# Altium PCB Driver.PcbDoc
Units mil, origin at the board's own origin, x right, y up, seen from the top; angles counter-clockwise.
Board outline 4275 x 2750 mil, 2 copper layers (Top Layer, Bottom Layer); 84 components, 44 nets, 226 pads, 191 vias.
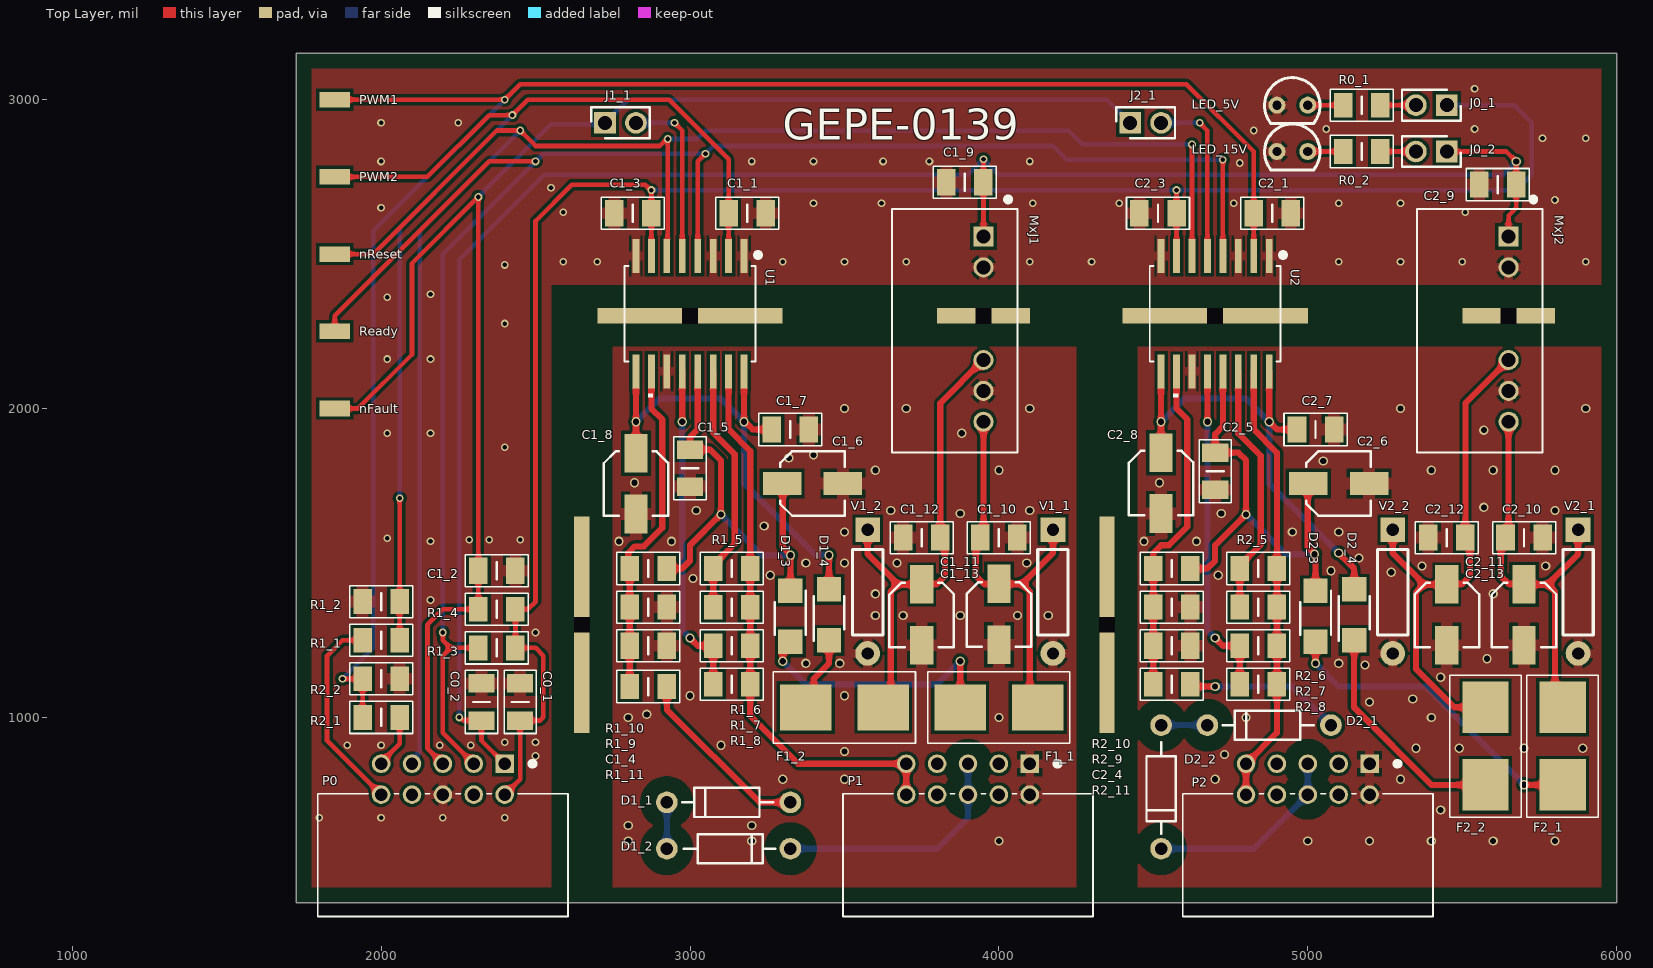
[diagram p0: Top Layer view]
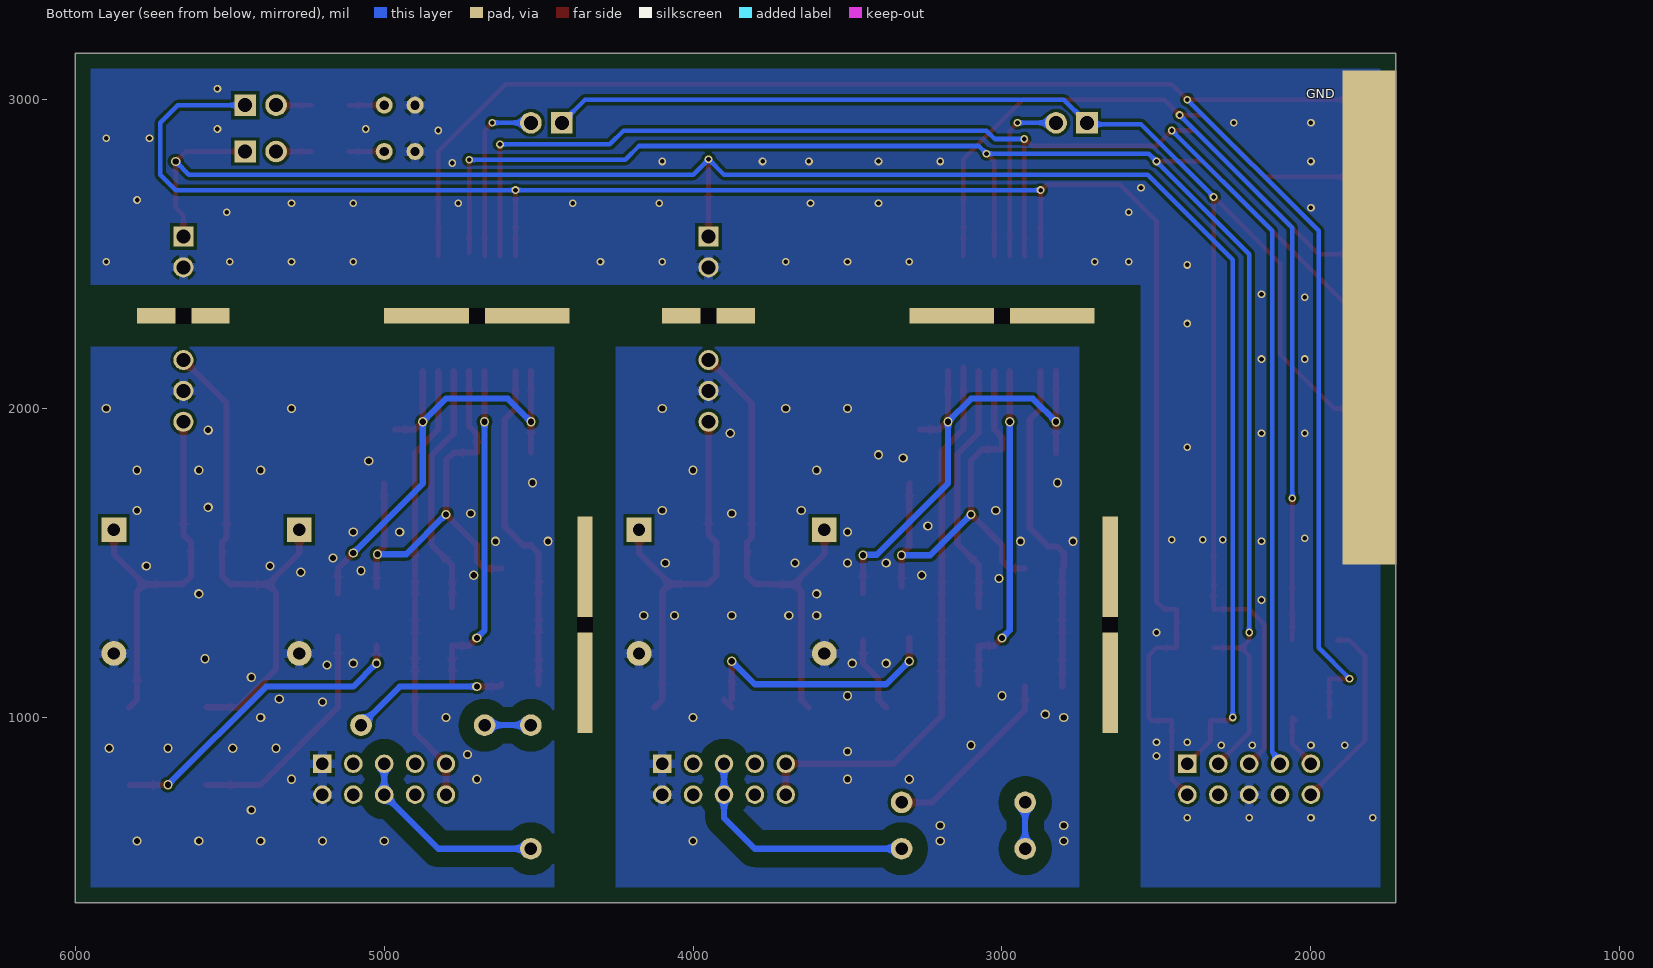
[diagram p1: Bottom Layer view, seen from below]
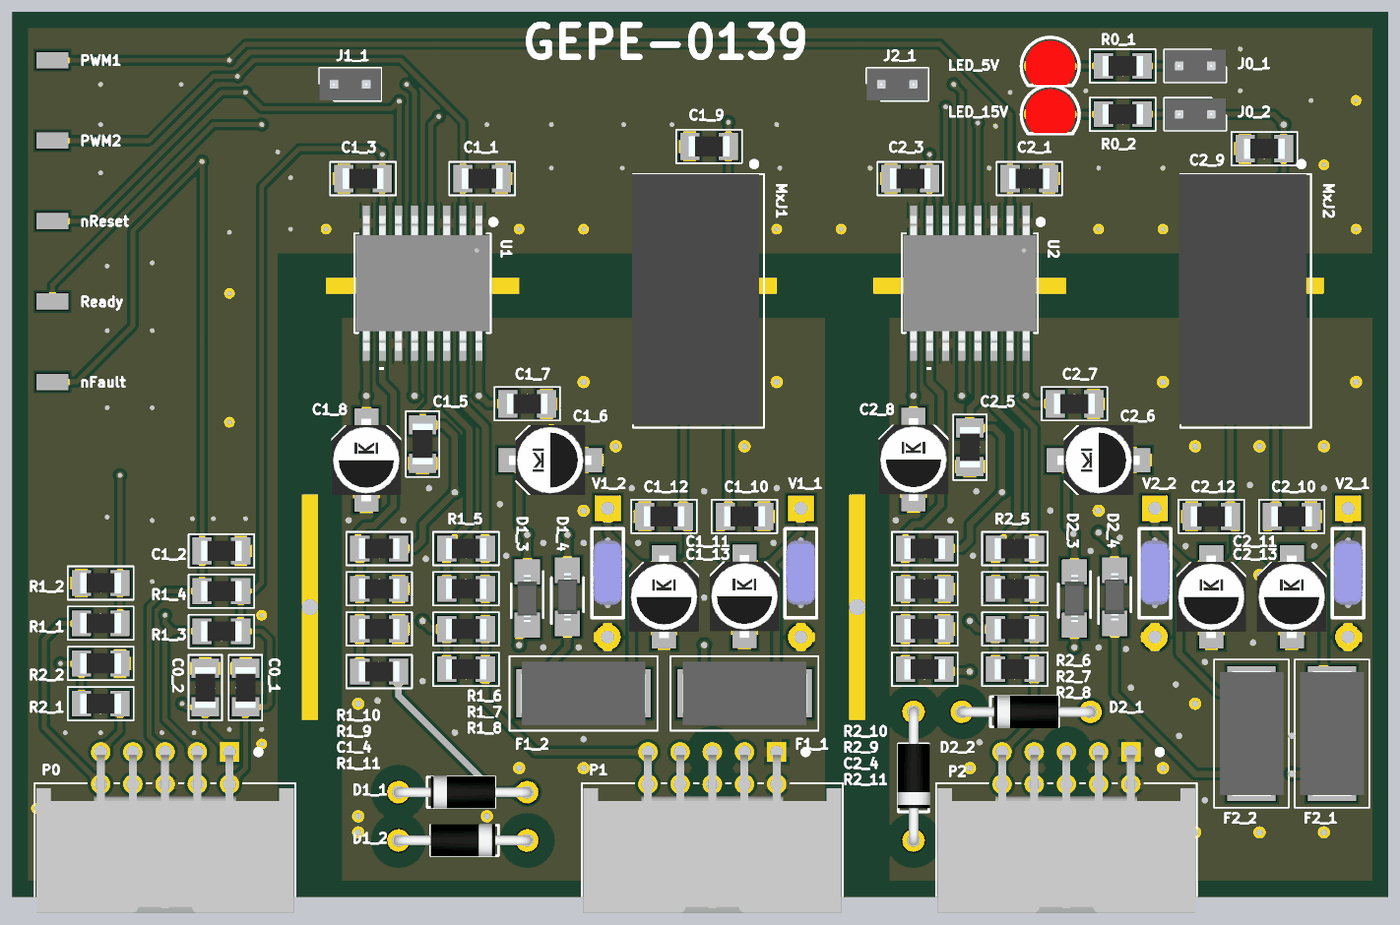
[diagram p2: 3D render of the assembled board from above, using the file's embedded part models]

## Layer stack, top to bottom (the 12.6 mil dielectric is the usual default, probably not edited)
Top Solder: solder mask 0.4, Solder Resist, Dk 3.5
Top Layer: signal copper 1.4
Dielectric 1: dielectric 12.6, FR-4, Dk 4.8
Bottom Layer: signal copper 1.4
Bottom Solder: solder mask 0.4, Solder Resist, Dk 3.5

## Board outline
1725,3150 6000,3150 6000,400 1725,400

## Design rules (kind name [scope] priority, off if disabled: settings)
Clearance Clearance_NetD1_2_1 [InNet('NetD1_2_1') vs InNet('GND_ISO1')] p1: gap=50 ignorepadtopadclearanceinfootprint=FALSE
Clearance Clearance_NetD2_1_1 [InNet('NetD2_1_1') vs InNet('GND_ISO2')] p2: gap=50 ignorepadtopadclearanceinfootprint=FALSE
Clearance Clearance_NetD2_2_1 [InNet('NetD2_2_1') vs InNet('GND_ISO2')] p3: gap=50 ignorepadtopadclearanceinfootprint=FALSE
Clearance Clearance_NetD1_1_1 [InNet('NetD1_1_1') vs InNet('GND_ISO1')] p4: gap=50 ignorepadtopadclearanceinfootprint=FALSE
Clearance "Stitching GND_ISO2" [IsStitchingVia and InNet('GND_ISO2') vs (IsVia and (Not IsStitchingVia)) Or IsPad] p5: gap=10 ignorepadtopadclearanceinfootprint=FALSE
Clearance [All] p6: gap=10 ignorepadtopadclearanceinfootprint=FALSE
ComponentClearance [All] p1: gap=-5 collisioncheckmode=3 verticalgap=10 showdistances=FALSE
DiffPairsRouting [All] p1: maxlimit=10 minlimit=10 mostfreqgap=10 substack1={C0840327-101B-4FFC-97E3-E8047B987EDC} toplayer_{c0840327-101b-4ffc-97e3-e8047b987edc}_minwidth=15 toplayer_{c0840327-101b-4ffc-97e3-e8047b987edc}_maxwidth=15 toplayer_{c0840327-101b-4ffc-97e3-e8047b987edc}_prefwidth=15 bottomlayer_{c0840327-101b-4ffc-97e3-e8047b987edc}_minwidth=15 bottomlayer_{c0840327-101b-4ffc-97e3-e8047b987edc}_maxwidth=15 bottomlayer_{c0840327-101b-4ffc-97e3-e8047b987edc}_prefwidth=15 toplayer_minwidth=15 toplayer_maxwidth=15 toplayer_prefwidth=15 bottomlayer_minwidth=15 bottomlayer_maxwidth=15 bottomlayer_prefwidth=15 substack2={2EBC8DE4-42E5-4D92-BB54-68FCB327EC1F} toplayer_{2ebc8de4-42e5-4d92-bb54-68fcb327ec1f}_minwidth=15 toplayer_{2ebc8de4-42e5-4d92-bb54-68fcb327ec1f}_maxwidth=15 toplayer_{2ebc8de4-42e5-4d92-bb54-68fcb327ec1f}_prefwidth=15 bottomlayer_{2ebc8de4-42e5-4d92-bb54-68fcb327ec1f}_minwidth=15 bottomlayer_{2ebc8de4-42e5-4d92-bb54-68fcb327ec1f}_maxwidth=15 bottomlayer_{2ebc8de4-42e5-4d92-bb54-68fcb327ec1f}_prefwidth=15 substack3={B410F142-04A1-4626-878C-5488EA430582} toplayer_{b410f142-04a1-4626-878c-5488ea430582}_minwidth=15 toplayer_{b410f142-04a1-4626-878c-5488ea430582}_maxwidth=15 toplayer_{b410f142-04a1-4626-878c-5488ea430582}_prefwidth=15 bottomlayer_{b410f142-04a1-4626-878c-5488ea430582}_minwidth=15 bottomlayer_{b410f142-04a1-4626-878c-5488ea430582}_maxwidth=15 bottomlayer_{b410f142-04a1-4626-878c-5488ea430582}_prefwidth=15 substack4={F83C5744-CF29-490E-B97B-F7943CBAD45F} toplayer_{f83c5744-cf29-490e-b97b-f7943cbad45f}_minwidth=15 toplayer_{f83c5744-cf29-490e-b97b-f7943cbad45f}_maxwidth=15 toplayer_{f83c5744-cf29-490e-b97b-f7943cbad45f}_prefwidth=15 bottomlayer_{f83c5744-cf29-490e-b97b-f7943cbad45f}_minwidth=15 bottomlayer_{f83c5744-cf29-490e-b97b-f7943cbad45f}_maxwidth=15 bottomlayer_{f83c5744-cf29-490e-b97b-f7943cbad45f}_prefwidth=15 substack5={FE27DC28-8263-47E9-9FA0-F4B9E94EB1D7} toplayer_{fe27dc28-8263-47e9-9fa0-f4b9e94eb1d7}_minwidth=15 toplayer_{fe27dc28-8263-47e9-9fa0-f4b9e94eb1d7}_maxwidth=15 toplayer_{fe27dc28-8263-47e9-9fa0-f4b9e94eb1d7}_prefwidth=15 bottomlayer_{fe27dc28-8263-47e9-9fa0-f4b9e94eb1d7}_minwidth=15 bottomlayer_{fe27dc28-8263-47e9-9fa0-f4b9e94eb1d7}_maxwidth=15 bottomlayer_{fe27dc28-8263-47e9-9fa0-f4b9e94eb1d7}_prefwidth=15 maxuncoupledlength=500
Height [All] p1: minheight=0 maxheight=10000 prefheight=500
HoleSize [All] p1: absolutevalues=TRUE maxlimit=1000 minlimit=1 maxpercent=80.000 minpercent=20.000
PolygonConnect [All] p1: connectstyle=Relief reliefconductorwidth=10 reliefentries=4 polygonreliefangle="90 Angle" airgapwidth=10
RoutingVias [All] p1: holewidth=20 width=30 viastyle="Through Hole" minholewidth=15 minwidth=25 maxholewidth=28 maxwidth=50
SilkToSilkClearance [All] p1: silktosilkclearance=0
SilkToSolderMaskClearance [IsPad] p1: minsilkscreentomaskgap=5 clearancetoexposedcopper=TRUE
SolderMaskExpansion [All] p1: expansion=4 istentingtop=FALSE
Width [All] p1: maxlimit=30 minlimit=15 preferedwidth=20 substack1={C0840327-101B-4FFC-97E3-E8047B987EDC} substack2={2EBC8DE4-42E5-4D92-BB54-68FCB327EC1F} substack3={B410F142-04A1-4626-878C-5488EA430582} substack4={F83C5744-CF29-490E-B97B-F7943CBAD45F} substack5={FE27DC28-8263-47E9-9FA0-F4B9E94EB1D7}
24 further rules are at their usual default settings.

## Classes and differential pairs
component class Driver2: ADUM2 C2_1 C2_3 C2_4 C2_5 C2_6 C2_7 C2_8 C2_9 C2_10 C2_11 C2_12 C2_13 D2_1 D2_2 D2_3 D2_4 F2_1 F2_2 MxJ2 P2 R2_1 R2_2 R2_5 R2_6 R2_7 R2_8 R2_9 R2_10 R2_11 U2 V2_1 V2_2
component class Driver: C0_1 C0_2 C1_1 C1_2 C1_3 C1_4 C1_5 C1_6 C1_7 C1_8 C1_9 C1_10 C1_11 C1_12 C1_13 D1_1 D1_2 D1_3 D1_4 F1_1 F1_2 GND J0_1 J0_2 J1_1 J2_1 LED_5V LED_15V MxJ1 nFault nReset P0 P1 PWM1 PWM2 R0_1 R0_2 R1_1 R1_2 R1_3 R1_4 R1_5 R1_6 R1_7 R1_8 R1_9 R1_10 R1_11 Ready U1 V1_1 V1_2

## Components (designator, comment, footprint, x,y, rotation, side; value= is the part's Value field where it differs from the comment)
C0_1 "CAP" CAP1206_SMD 2450,1050 r90 top
C0_2 "CAP" CAP1206_SMD 2325,1050 r90 top
C1_1 "CAP" CAP1206_SMD 3185,2632.16 r0 top
C1_2 "CAP" CAP1206_SMD 2375,1475 r0 top
C1_3 "CAP" CAP1206_SMD 2815,2632.16 r180 top
C1_4 "CAP" CAP1206_SMD 2865,1232.16 r0 top
C1_5 "CAP" CAP1206_SMD 3000,1807.16 r270 top
C1_6 "CAP" CAP_ELETRO_SMD_6.3X7.7 3396.57,1757.16 r0 top
C1_7 "CAP" CAP1206_SMD 3325,1932.16 r0 top
C1_8 "CAP" CAP_ELETRO_SMD_6.3X7.7 2825,1757.16 r270 top
C1_9 "CAP" CAP1206_SMD 3890,2732.16 r180 top
C1_10 "CAP" CAP1206_SMD 4000,1582.16 r0 top
C1_11 "CAP" CAP_ELETRO_SMD_6.3X7.7 4000,1333.73 r270 top
C1_12 "CAP" CAP1206_SMD 3750,1582.16 r180 top
C1_13 "CAP" CAP_ELETRO_SMD_6.3X7.7 3750,1332.16 r270 top
C2_1 "CAP" CAP1206_SMD 4885,2632.16 r0 top
C2_3 "CAP" CAP1206_SMD 4515,2632.16 r180 top
C2_4 "CAP" CAP1206_SMD 4560,1232.16 r0 top
C2_5 "CAP" CAP1206_SMD 4700,1797.16 r270 top
C2_6 "CAP" CAP_ELETRO_SMD_6.3X7.7 5100,1757.16 r0 top
C2_7 "CAP" CAP1206_SMD 5025,1932.16 r0 top
C2_8 "CAP" CAP_ELETRO_SMD_6.3X7.7 4525,1758.73 r270 top
C2_9 "CAP" CAP1206_SMD 5615,2725 r180 top
C2_10 "CAP" CAP1206_SMD 5700,1582.16 r0 top
C2_11 "CAP" CAP_ELETRO_SMD_6.3X7.7 5700,1332.16 r270 top
C2_12 "CAP" CAP1206_SMD 5450,1582.16 r180 top
C2_13 "CAP" CAP_ELETRO_SMD_6.3X7.7 5450,1332.16 r270 top
D1_1 "TLHR5400-AS12Z" DIODE_TH_10.1 2925,725 r0 top
D1_2 "TLHR5400-AS12Z" DIODE_TH_10.1 3325,575 r180 top
D1_3 "TLHR5400-AS12Z" DIODE_SMD_SOD123 3325,1327.16 r270 top
D1_4 "TLHR5400-AS12Z" DIODE_SMD_SOD123 3450,1332.16 r90 top
D2_1 "TLHR5400-AS12Z" DIODE_TH_10.1 4675,975 r0 top
D2_2 "TLHR5400-AS12Z" DIODE_TH_10.1 4525,575 r90 top
D2_3 "TLHR5400-AS12Z" DIODE_SMD_SOD123 5025,1327.16 r270 top
D2_4 "TLHR5400-AS12Z" DIODE_SMD_SOD123 5150,1332.16 r90 top
F1_1 "Fuse_0154" FUSE_0154 4000,1032.16 r180 top
F1_2 "Fuse_0154" FUSE_0154 3500,1032.16 r180 top
F2_1 "Fuse_0154" FUSE_0154 5825,907.16 r270 top
F2_2 "Fuse_0154" FUSE_0154 5575,907.16 r270 top
GND "TB004-508-02BE" TestPoint 1810,2295 r0 top
J0_1 "TB004-508-02BE" HEADER_MALE_TH_2P_2.54 5450,2982.16 r90 top
J0_2 "TB004-508-02BE" HEADER_MALE_TH_2P_2.54 5450,2832.16 r90 top
J1_1 "TB004-508-02BE" HEADER_MALE_TH_2P_2.54 2725,2925 r270 top
J2_1 "TB004-508-02BE" HEADER_MALE_TH_2P_2.54 4425,2925 r270 top
LED_5V "TLHR5400-AS12Z" "LED_TH_2.54 (SMALL)" 4900,2982.16 r0 top
LED_15V "TLHR5400-AS12Z" "LED_TH_2.54 (SMALL)" 4900,2832.16 r0 top
MxJ1 "MGJ2D152005SC" MGJ2_MUR 3950,2557.16 r270 top
MxJ2 "MGJ2D152005SC" MGJ2_MUR 5650,2557.16 r270 top
nFault "TB004-508-02BE" TESTPOINT 1850,2000 r270 top
nReset "TB004-508-02BE" TESTPOINT 1850,2500 r270 top
P0 "5103311-1" CONN_5103311-1_TYC 2400,750 r180 top
P1 "5103311-1" CONN_5103311-1_TYC 4100,750 r180 top
P2 "5103311-1" CONN_5103311-1_TYC 5200,750 r180 top
PWM1 "TB004-508-02BE" TESTPOINT 1850,3000 r270 top
PWM2 "TB004-508-02BE" TESTPOINT 1850,2750 r270 top
R0_1 "" RESIS_SMD_1206 5175,2982.16 r0 top
R0_2 "" RESIS_SMD_1206 5175,2832.16 r0 top
R1_1 "" RESIS_SMD_1206 2000,1250 r0 top
R1_2 "" RESIS_SMD_1206 2000,1375 r0 top
R1_3 "" RESIS_SMD_1206 2375,1225 r0 top
R1_4 "" RESIS_SMD_1206 2375,1350 r0 top
R1_5 "Res1" RESIS_SMD_1206 3135,1482.14 r0 top
R1_6 "Res1" RESIS_SMD_1206 3135,1357.14 r0 top
R1_7 "Res1" RESIS_SMD_1206 3135,1232.14 r0 top
R1_8 "Res1" RESIS_SMD_1206 3135,1107.14 r0 top
R1_9 "" RESIS_SMD_1206 2865,1357.16 r180 top
R1_10 "" RESIS_SMD_1206 2865,1482.16 r0 top
R1_11 "" RESIS_SMD_1206 2865,1100 r0 top
R2_1 "" RESIS_SMD_1206 2000,1000 r180 top
R2_2 "" RESIS_SMD_1206 2000,1125 r180 top
R2_5 "Res1" RESIS_SMD_1206 4840,1482.16 r0 top
R2_6 "Res1" RESIS_SMD_1206 4840,1357.16 r0 top
R2_7 "Res1" RESIS_SMD_1206 4840,1232.16 r0 top
R2_8 "Res1" RESIS_SMD_1206 4840,1107.16 r0 top
R2_9 "" RESIS_SMD_1206 4560,1357.16 r180 top
R2_10 "" RESIS_SMD_1206 4560,1482.16 r0 top
R2_11 "" RESIS_SMD_1206 4560,1107.16 r0 top
Ready "TB004-508-02BE" TESTPOINT 1850,2250 r90 top
U1 "ADUM4135BRWZ" RW_16_ADI-M 3000,2307.16 r270 top
U2 "ADUM4135BRWZ" RW_16_ADI-M 4700,2307.16 r270 top
V1_1 "B72220S131K101" VARIST 4175,1407.16 r270 top
V1_2 "B72220S131K101" VARIST 3575,1407.16 r270 top
V2_1 "B72220S131K101" VARIST 5875,1407.16 r270 top
V2_2 "B72220S131K101" VARIST 5275,1407.16 r270 top

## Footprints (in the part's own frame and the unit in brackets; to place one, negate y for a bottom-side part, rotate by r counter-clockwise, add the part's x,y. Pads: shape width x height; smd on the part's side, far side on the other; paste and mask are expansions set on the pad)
CAP1206_SMD [mil]
  rect 60x85 smd: 1(-60,0) 2(60,0)
  silkscreen extent -102,-52 102,52, body extent -63,-31 63,31, height 26
CAP_ELETRO_SMD_6.3X7.7 [mm]
  rect 3.175x1.905 smd: 1(-2.5,0) 2(2.5,0)
  silkscreen extent -2.65,-2.65 2.65,2.65, body extent -3.25,-2.75 3.25,2.75, height 5.74
CONN_5103311-1_TYC [mil]
  rect 60x60 hole 40 mask+0: 1(0,-100)
  round 60 hole 40 mask+0: 2(0,0) 3(100,-100) 4(100,0) 5(200,-100) 6(200,0) 7(300,-100) 8(300,0) 9(400,-100) 10(400,0)
  silkscreen extent -205,-101 605,395, body extent -200,-90 600,400, height 370
DIODE_SMD_SOD123 [mm]
  rect 2x2 smd: 1(-2.1,0) 2(2.1,0)
  silkscreen extent -2.13,-1.27 1.52,1.27, body extent -1.85,-0.77 1.85,0.78, height 1.45
DIODE_TH_10.1 [mil]
  round 70 hole 40: 1(0,0) 2(400,0)
  silkscreen extent 49,-47 345,47, body extent -15,-51 415,50, height 100
FUSE_0154 [mil]
  rect 167x150 smd: 1(-125.59,0) 2(125.59,0)
  silkscreen extent -230,-116 230,116, body extent -194,-99 194,99, height 154
HEADER_MALE_TH_2P_2.54 [mil]
  rect 70x70 hole 45: 1(0,0)
  round 70 hole 45: 2(0,100)
  silkscreen extent -50,-45 50,145, body extent -50,-45 50,145, height 338
"LED_TH_2.54 (SMALL)" [mil]
  round 55 hole 30: 1(0,0) 2(100,0)
  silkscreen extent -40,-60 140,89, body extent -28,-59 129,79, height 212
MGJ2_MUR [mil]
  rect 65x65 hole 45 mask+0: 1(0,0)
  round 65 hole 45 mask+0: 2(100,0) 5(400,0) 6(500,0) 7(600,0)
  silkscreen extent -121,-296 699,110, body extent -89,-300 689,96, height 502
RESIS_SMD_1206 [mil]
  rect 60x80 smd: 1(-60,0) 2(60,0)
  silkscreen extent -102,-52 102,52, body extent -63,-31 63,31, height 30
RW_16_ADI-M [mil]
  rect 110x22 smd paste+0 mask+0: 1(-186.5,175) 2(-186.5,125) 3(-186.5,75) 4(-186.5,25) 5(-186.5,-25) 6(-186.5,-75) 7(-186.5,-125) 8(-186.5,-175) 9(186.5,-175) 10(186.5,-125) 11(186.5,-75) 12(186.5,-25) 13(186.5,25) 14(186.5,75) 15(186.5,125) 16(186.5,175)
  silkscreen extent -191,-212 270,221, body extent -209,-206 209,206, height 104
TestPoint [mil]
  rect 175x1600 smd far side: 1(0,0)
TESTPOINT [mm]
  rect 1.28x2.5 smd: 1(0,0)
VARIST [mil]
  rect 80x80 hole 40: 1(-200,0)
  round 80 hole 40: 2(200,0)
  silkscreen extent -137,-49 140,49, body extent -110,-45 110,45, height 250

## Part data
C0_1 C0_2 C1_1 C1_2 C1_3 C1_4 C1_5 C1_6 C1_7 C1_8 C1_9 C1_10 C1_11 C1_12 C1_13 C2_1 C2_3 C2_4 C2_5 C2_6 C2_7 C2_8 C2_9 C2_10 C2_11 C2_12 C2_13: "Capacitor", Manufacturer_Name=Kemet, Manufacturer_Part_Number=C1206X475K3RACAUTO7210, Mouser Part Number=80-C1206X475K3RAUTLR
D1_1 D1_2 D1_3 D1_4 D2_1 D2_2 D2_3 D2_4: library part Diode, "Diode", Manufacturer_Name=Vishay
F1_1 F1_2 F2_1 F2_2: "Fuse", Manufacturer_Name=LITTELFUSE, Manufacturer_Part_Number=0154002.DRL, Mouser2 Part Number=576-0154002.DRL
GND nFault nReset PWM1 PWM2 Ready: library part TestPoint, "Connector", Manufacturer_Name="CUI Devices", Mouser Part Number=490-TB004-508-02BE
J0_1 J0_2 J1_1 J2_1: library part Con_Header_2P, "Connector", Manufacturer_Name="CUI Devices", Mouser Part Number=490-TB004-508-02BE
LED_5V LED_15V: library part LED, "LED", Manufacturer_Name=Vishay
MxJ1 MxJ2: "No Description Available", Mfr_Name=Murata
P0 P1 P2: library part Con_Header_5103311-1, "No Description Available", Mfr_Name="TE Connectivity"
R0_1 R0_2 R1_1 R1_2 R1_3 R1_4 R1_5 R1_6 R1_7 R1_8 R1_9 R1_10 R1_11 R2_1 R2_2 R2_5 R2_6 R2_7 R2_8 R2_9 R2_10 R2_11: library part Resistor, "Resistor"
U1 U2: "No Description Available", Mfr_Name="Analog Devices Inc"
V1_1 V1_2 V2_1 V2_2: library part Varistor, "No Description Available", Mfr_Name=TDK

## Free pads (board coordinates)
  rect 50x700 hole 50 square mask+0: 1(2650,1300) 1(4350,1300)
  rect 600x50 hole 50 square mask+0: 1(3000,2300) 1(4700,2300)
  rect 300x50 hole 50 square mask+0: 1(3950,2300) 1(5650,2300)

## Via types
v1: diameter 30, hole 20, Top Layer to Bottom Layer, tented top, 75 vias
v2: diameter 25, hole 15, Top Layer to Bottom Layer, tented top, 63 vias
v3: diameter 30, hole 20, Top Layer to Bottom Layer, 33 vias
v4: diameter 25, hole 15, Top Layer to Bottom Layer, 20 vias

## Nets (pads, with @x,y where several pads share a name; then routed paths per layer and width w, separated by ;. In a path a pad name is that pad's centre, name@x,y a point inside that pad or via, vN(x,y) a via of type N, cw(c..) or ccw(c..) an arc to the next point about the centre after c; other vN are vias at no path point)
GND: C0_1.2 C0_2.2 C1_1.2 C1_2.2 C1_3.2 C1_9.2 C2_1.2 C2_3.2 C2_9.2 GND.1 LED_5V.1 LED_15V.1 MxJ1.2 MxJ2.2 P0.6 R1_2.1 R2_2.1 U1.1 U1.3 U1.8 U2.1 U2.3 U2.8
  other v2: 1890,910 2000,910 2190,910 2290,910 2400,920 2500,920 2160,1380 2160,1570 2285,1575 2350,1575 2450,1575 2020,1580 2020,1920 2160,1920 2020,2160 2160,2160 2020,2360 2160,2370 2400,2465 2590,2475 2590,2635 5510,2635 2000,2650 3400,2665 3620,2665 4110,2665 4390,2665 4760,2665 5100,2665 5300,2665 2550,2715 4780,2795 2000,2800 3200,2800 3400,2800 3625,2800 3775,2800 4100,2800 5760,2875 4825,2900 5060,2905 5540,2905 2000,2925 2250,2925 5540,3035
  other v4: 1800,675 2000,675 2200,675 2400,675 2500,875 2500,1275 2400,1875 2400,2275 2700,2475 3300,2475 3500,2475 3700,2475 4100,2475 4300,2475 5100,2475 5300,2475 5500,2475 5900,2475 5800,2675 5900,2875
GND_ISO1: C1_4.2 C1_5.2 C1_6.2 C1_7.2 C1_8.2 C1_10.2 C1_11.2 C1_12.2 C1_13.2 MxJ1.6 P1.1 P1.2 R1_9.1 U1.11 V1_1.2 V1_2.2
  other v1: 3500,890 3100,910 2860,1010 3000,1070 3500,1070 3375,1175 3485,1175 3600,1330 3690,1330 3875,1330 4060,1330 4160,1330 3010,1450 3260,1460 3375,1500 3500,1500 3670,1500 4090,1500 2770,1570 2940,1570 3240,1620 3875,1660 3020,1670 3650,1670 4100,1670 2820,1760 3320,1840 3880,1920
  other v3: 2800,600 3200,600 4000,600 2800,650 3200,650 3300,800 3500,800 2800,1000 4000,1000 3600,1400 3500,1600 3600,1800 4000,1800 3400,1850 3500,2000 3700,2000 4100,2000
GND_ISO2: C2_4.2 C2_5.2 C2_6.2 C2_7.2 C2_8.2 C2_10.2 C2_11.2 C2_12.2 C2_13.2 MxJ2.6 P2.1 P2.2 R2_9.1 U2.11 V2_1.2 V2_2.2
  other v1: 5430,700 4730,880 5350,900 5490,900 5700,900 5890,900 5200,1050 5340,1060 5430,1130 5185,1170 5100,1175 5580,1190 4710,1460 5270,1470 5075,1475 5370,1490 5770,1490 5165.83,1515.83 4470,1570 4640,1570 4950,1600 4720,1660 5800,1670 5570,1680 4520,1760 5050,1830 5570,1930
  other v3: 5000,600 5200,600 5400,600 5600,600 5800,600 4700,800 5300,800 4800,1000 5400,1000 5600,1400 5100,1600 5400,1800 5600,1800 5800,1800 5300,2000 5900,2000
NetC0_1_1: C0_1.1 C1_3.1 C2_3.1 J0_1.1 P0.2 R1_3.2 R1_4.2 U1.7 U2.7 | length 6268.2
  Top Layer w15: P0.2 2450,800 C0_1.1 2515,990 2525,1000 2525,1200 2500,1225 R1_3.2 R1_4.2 2475,1350 2500,1375 2500,2607.16 2617.84,2725 2854.45,2725 2872.29,2707.16 v2(2875,2707.16) C1_3.1 U1.7 ; U2.7 C2_3.1 v2(4575,2707.16)
  Bottom Layer w15: v2(2875,2707.16) v2(4575,2707.16) 5675,2707.16 5725,2757.16 5725,2925 5667.84,2982.16 J0_1.1
NetC0_2_1: C0_2.1 C1_9.1 C2_9.1 J0_2.1 MxJ1.1 MxJ2.1 P0.1 | length 6065.7
  Top Layer w15: v2(2253.12,1000) 2255.83,1000 2265.83,990 C0_2.1 2325,925 P0.1 ; MxJ1.1 C1_9.1 v2(3950,2807.16) ; J0_2.1 5642.84,2832.16 v1(5675,2800) C2_9.1 5675,2650 5650,2625 MxJ2.1
  Bottom Layer w15: v2(2253.12,1000) 2253.12,2482.16 2528.12,2757.16 3900,2757.16 v2(3950,2807.16) 4000,2757.16 5632.16,2757.16 v1(5675,2800)
NetC1_1_1: C1_1.1 PWM2.1 R1_1.2 R1_2.2 U1.2 | length 3623.1
  Top Layer w15: PWM2.1 2150,2750 2350,2950 v2(2425,2950) 2475,3000 2932.16,3000 3125,2807.16 C1_1.1 U1.2 ; R1_1.2 R1_2.2 v2(2060,1710)
  Bottom Layer w15: v2(2060,1710) 2060,2585 v2(2425,2950)
NetC1_2_1: C1_2.1 J1_1.1 J2_1.1 nFault.1 P0.5 R1_4.1 | length 5184.5
  Top Layer w15: nFault.1 1925,2000 2100,2175 2100,2470 v2(2315,2685) C1_2.1 R1_4.1 2200,1350 2150,1300 2150,900 P0.5
  Bottom Layer w15: v2(2315,2685) 2550,2920 2720,2920 J1_1.1 2800,3000 4350,3000 J2_1.1
NetC1_4_1: C1_4.1 R1_9.2 R1_10.1 R1_11.1 U1.10 | length 1099.5
  Top Layer w20: R1_11.1 C1_4.1 R1_9.2 R1_10.1 2800,1487.16 2800,1532.16 2821.42,1553.58 2850,1553.58 2910,1613.58 2910,1965 2875,2000 U1.10
NetC1_5_1: C1_5.1 C1_6.1 D1_3.1 R1_10.2 U1.13 | length 1456
  Top Layer w20: R1_10.2 2975,1482.16 3000,1507.16 3000,1557.16 v1(3100,1657.16) 3100,1832.16 3065,1867.16 C1_5.1 3000,1907.16 3025,1932.16 U1.13 ; C1_6.1 3300,1755.31 3300,1552.71 3325,1527.71 D1_3.1@3325,1422.16
  Bottom Layer w20: v1(3100,1657.16) 3232.16,1525 v1(3325,1525)
NetC1_7_1: C1_7.1 C1_8.1 D1_4.2 U1.9 U1.16 | length 1634.9
  Top Layer w20: C1_8.1 v1(2825,1957.16) U1.9 ; U1.16 v1(3175,1957.16) 3177.71,1957.16 3202.71,1932.16 C1_7.1 ; D1_4.2@3450,1402.33 v1(3450,1525)
  Bottom Layer w20: v1(2825,1957.16) 2900,2032.16 3100,2032.16 v1(3175,1957.16) 3175,1757.16 3405.24,1526.91 3448.09,1526.91 v1(3450,1525)
NetC1_10_1: C1_10.1 C1_11.1 F1_1.1 MxJ1.7 V1_1.1 | length 1307.1
  Top Layer w20: MxJ1.7 3950,1592.16 C1_10.1 3925,1567.16 3925,1458.87 3951.72,1432.16 C1_11.1 4075,1432.16 ; F1_1.1 4100,1057.75 4100,1407.16 4075,1432.16 ; V1_1.1 4175,1532.16 4075,1432.16
NetC1_12_1: C1_12.1 C1_13.1 F1_2.1 MxJ1.5 V1_2.1 | length 1562.4
  Top Layer w20: V1_2.1 3575,1529.01 3673.43,1430.58 ; F1_2.1 3650,1056.57 3650,1407.16 3673.43,1430.58 ; MxJ1.5 3810,2017.16 C1_12.1 3825,1567.16 3825,1457.16 3800,1432.16 3751.57,1432.16 C1_13.1 3673.43,1430.58
NetC2_1_1: C2_1.1 PWM1.1 R2_1.2 R2_2.2 U2.2 | length 5706.9
  Top Layer w15: PWM1.1 v2(2400,3000) 2450,3050 4607.16,3050 4825,2832.16 C2_1.1 U2.2 ; v2(1875,1125) R2_2.2 R2_1.2
  Bottom Layer w15: v2(1875,1125) 1975,1225 1975,2575 v2(2400,3000)
NetC2_4_1: C2_4.1 R2_9.2 R2_10.1 R2_11.1 U2.10 | length 1088.3
  Top Layer w20: R2_11.1 C2_4.1 R2_9.2 R2_10.1 4500,1532.16 4525,1557.16 4550.13,1557.16 4610,1617.02 4610,1965 4575,2000 U2.10
NetC2_5_1: C2_5.1 C2_6.1 D2_3.1 R2_10.2 U2.13 | length 1463.2
  Top Layer w20: R2_10.2 4675,1482.16 4700,1507.16 4700,1557.16 v1(4800,1657.16) 4800,1832.16 4775,1857.16 C2_5.1 4700,1917.16 4725,1942.16 U2.13 ; C2_6.1 5000,1755.58 5000,1552.71 5024.98,1527.72 5024.98,1525.02 5023.63,1523.66 5025,1522.29 D2_3.1@5025,1422.16
  Bottom Layer w20: v1(4800,1657.16) 4928.87,1528.28 v1(5021.72,1528.28)
NetC2_7_1: C2_7.1 C2_8.1 D2_4.2 U2.9 U2.16 | length 1608.4
  Top Layer w20: C2_8.1 v1(4525,1957.16) U2.9 ; U2.16 v1(4875,1957.16) 4900,1932.16 C2_7.1 ; v1(5100,1532.16) 5150,1482.16 D2_4.2@5150,1402.15
  Bottom Layer w20: v1(4525,1957.16) 4600,2032.16 4800,2032.16 v1(4875,1957.16) 4875,1757.16 v1(5100,1532.16)
NetC2_10_1: C2_10.1 C2_11.1 F2_1.1 MxJ2.7 V2_1.1 | length 1309
  Top Layer w20: MxJ2.7 5650,1592.16 C2_10.1 5625,1567.16 5625,1457.16 5650,1432.16 5698.43,1432.16 C2_11.1 5776.57,1430.58 ; F2_1.1@5825.59,1032.16 5800,1057.75 5800,1407.16 5776.57,1430.58 ; V2_1.1 5875,1529.01 5776.57,1430.58
NetC2_12_1: C2_12.1 C2_13.1 F2_2.1 MxJ2.5 V2_2.1 | length 1703.2
  Top Layer w20: V2_2.1 5275,1532.16 5376.57,1430.58 ; F2_2.1 5474.41,1032.75 5350,1157.16 5350,1404.01 5376.57,1430.58 ; MxJ2.5 5510,2017.16 C2_12.1 5525,1567.16 5525,1457.16 5500,1432.16 5451.57,1432.16 C2_13.1 5376.57,1430.58
NetD1_1_1: D1_1.1 D1_2.2 | length 150
  Bottom Layer w20: D1_2.2 D1_1.1
NetD1_1_2: D1_1.2 R1_11.2 | length 599.3
  Top Layer w20: R1_11.2 2925,1025 3225,725 D1_1.2
NetD1_2_1: D1_2.1 P1.5 P1.6 | length 791.4
  Bottom Layer w20: D1_2.1 3800,575 3900,675 P1.6 P1.5
NetD1_3_2: D1_3.2 F1_1.2 | length 872.7
  Top Layer w20: v1(3300,1182.16) D1_3.2@3300,1257.16 ; F1_1.2 F1_1.2@3900,1057.75 ; F1_1.2@3875,1057.75 v1(3875,1182.16)
  Bottom Layer w20: v1(3300,1182.16) 3375,1107.16 3800,1107.16 v1(3875,1182.16)
NetD1_4_1: D1_4.1 F1_2.2 | length 248.6
  Top Layer w20: F1_2.2 3400.44,1058.19 3400.44,1125.44 3450,1175 D1_4.1
NetD2_1_1: D2_1.1 D2_2.2 | length 174.5
  Top Layer w20: D2_2.2 D2_2.2@4549.47,975
  Bottom Layer w20: D2_2.2 D2_1.1
NetD2_1_2: D2_1.2 R2_11.2 | length 509.7
  Top Layer w20: R2_11.2 4627.16,1100 v1(4700,1100)
  Bottom Layer w20: v1(4700,1100) 4950,1100 D2_1.2
NetD2_2_1: D2_2.1 P2.5 P2.6 | length 647.5
  Bottom Layer w20: D2_2.1 4825,575 P2.6 P2.5
NetD2_3_2: D2_3.2 F2_1.2 | length 1020.1
  Top Layer w20: v1(5025,1175) D2_3.2@5025,1232.16 ; v1(5700,782.16) 5700.59,781.57 F2_1.2
  Bottom Layer w20: v1(5025,1175) 5100,1100 5382.16,1100 v1(5700,782.16)
NetD2_4_1: D2_4.1 F2_2.2 | length 758.2
  Top Layer w20: D2_4.1@5150,1261.6 5150,1032.16 5400,782.16 5400.59,781.57 F2_2.2
NetJ0_1_2: J0_1.2 R0_1.2 | length 115
  Top Layer w15: R0_1.2 J0_1.2
NetJ0_2_2: J0_2.2 R0_2.2 | length 115
  Top Layer w15: R0_2.2 J0_2.2
NetJ1_1_2: J1_1.2 U1.5 | length 576.5
  Top Layer w15: v2(2950,2925) 2975,2900 U1.5
  Bottom Layer w15: J1_1.2@2825,2900 J1_1.2@2830,2905 ; J1_1.2 v2(2950,2925) v2@2950,2922.29
NetJ2_1_2: J2_1.2 U2.5 | length 577.1
  Top Layer w15: v2(4650,2925) 4675,2900 U2.5
  Bottom Layer w15: J2_1.2@4525,2900 4550,2925 v2(4650,2925)
NetLED_5V_2: LED_5V.2 R0_1.1 | length 115
  Top Layer w15: LED_5V.2 R0_1.1
NetLED_15V_2: LED_15V.2 R0_2.1 | length 115
  Top Layer w15: LED_15V.2 R0_2.1
NetnReset_1: nReset.1 P0.7 U1.6 U2.6 | length 5937.7
  Top Layer w15: nReset.1 1975,2500 2375,2900 v2(2450,2900) 2500,2850 2902.29,2850 2924.79,2872.5 v2(2927.5,2872.5) 2927.5,2496.16 U1.6 ; U2.6 4623.75,2494.91 4625,2496.16 v2(4625,2855)
  Bottom Layer w15: P0.7 2100,862.18 2125,887.18 2125,2575 v2(2450,2900) ; v2(2927.5,2872.5) 3023.11,2872.5 3050.3,2899.7 4225.3,2899.7 4270,2855 v2(4625,2855)
NetP0_3: P0.3 R1_3.1 Ready.1 U1.4 U2.4 | length 6040.9
  Top Layer w15: Ready.1 1850,2300 2350,2800 v2(2500,2800) ; v2(2200,1275) 2200,1250 2225,1225 ; P0.3 2200,950 2200,1200 2225,1225 ; R1_3.1 2225,1225 ; U1.4 3025,2800 v2(3050,2825) ; U2.4@4725,2503.66 v2(4725,2805)
  Bottom Layer w15: v2(2200,1275) 2200,2500 v2(2500,2800) 2525,2825 v2(3050,2825) 3075,2850 4175,2850 4220,2805 v2(4725,2805)
NetP0_9: P0.9 R2_1.1 | length 189
  Top Layer w15: P0.9 2000,854.25 2060,914.25 R2_1.1 R2_1.1@2050,990
NetP0_10: P0.10 R1_1.1 | length 633.2
  Top Layer w15: R1_1.1@1915,1250 1875,1250 1825,1200 1825,925 P0.10
NetP1_9: P1.9 P1.10 R1_5.2 R1_6.2 R1_7.2 R1_8.2 U1.15 | length 1825.4
  Top Layer w20: U1.15@3125,2132.16 U1.15 3125,1932.16 3195,1862.16 R1_5.2 R1_6.2 R1_7.2 R1_8.2 3195,1005 3350,850 P1.9 P1.10
NetP2_9: P2.9 P2.10 R2_5.2 R2_6.2 R2_7.2 R2_8.2 U2.15 | length 1443.1
  Top Layer w20: P2.10 P2.9 4900,950 R2_8.2 R2_7.2 R2_6.2 R2_5.2 4900,1857.16 4825,1932.16 U2.15
NetR1_5_1: R1_5.1 R1_6.1 U1.14 | length 821.5
  Top Layer w20: R1_6.1 R1_5.1 3075,1492.14 3145.01,1562.15 3145,1852.16 3075,1922.16 U1.14
NetR1_7_1: R1_7.1 R1_8.1 U1.12 | length 1084.2
  Top Layer w20: v1(2975,1957.16) U1.12 ; v1(3000,1257.16) 3025.01,1232.14 R1_7.1 R1_8.1
  Bottom Layer w20: v1(2975,1957.16) 2975,1282.16 v1(3000,1257.16)
NetR2_5_1: R2_5.1 R2_6.1 U2.14 | length 821.5
  Top Layer w20: U2.14 4775,1919.66 4847.5,1847.16 4847.5,1559.66 4780,1492.16 R2_5.1 R2_6.1
NetR2_7_1: R2_7.1 R2_8.1 U2.12 | length 1089.2
  Top Layer w20: v1(4675,1957.16) U2.12 ; v1(4700,1257.16) 4725,1232.16 R2_7.1 R2_8.1
  Bottom Layer w20: v1(4675,1957.16) 4675,1282.16 v1(4700,1257.16)
pads on no net: P0.4 P0.8 P1.3 P1.4 P1.7 P1.8 P2.3 P2.4 P2.7 P2.8

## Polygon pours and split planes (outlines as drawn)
GND_ISO2 on Top Layer "GND_ISO2_L01_P140" (solid, remove dead copper, pour order 140): 4450,2200 4450,450 5950,450 5950,2200
GND_ISO1 on Top Layer "GND_ISO1_L01_P128" (solid, remove dead copper, pour order 128): 2750,450 4250,450 4250,2200 2750,2200
GND on Top Layer "GND_L01_P126" (solid, remove dead copper, pour order 126): 2550,450 1775,450 1775,3100 5950,3100 5950,2400 2550,2400
GND_ISO1 on Bottom Layer "GND_ISO1_L02_P130" (solid, remove dead copper, pour order 130): 4250,450 4250,2200 2750,2200 2750,450
GND_ISO2 on Bottom Layer "GND_ISO2_L02_P138" (solid, remove dead copper, pour order 138): 4450,450 5950,450 5950,2200 4450,2200
GND on Bottom Layer "GND_L02_P134" (solid, remove dead copper, pour order 134): 2550,450 1775,450 1775,3100 5950,3100 5950,2400 2550,2400

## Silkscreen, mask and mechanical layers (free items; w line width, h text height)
Top Overlay:
  text "GEPE-0139" at 3300,2870 h100
Board Outline:
  lines w10: 6001.07,401.07 6000,400 ; 6000,400 6000,3127.48 6000,3145.94 5997.97,3147.97 5979.6,3147.97 1747.26,3147.97 1727.03,3147.97 1725,3145.94 1725,3125.71 1725,400 6000,400

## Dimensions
4250,355 to 6550,3500 on Mechanical 7
2400,400 to 4305,400 on Mechanical 7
